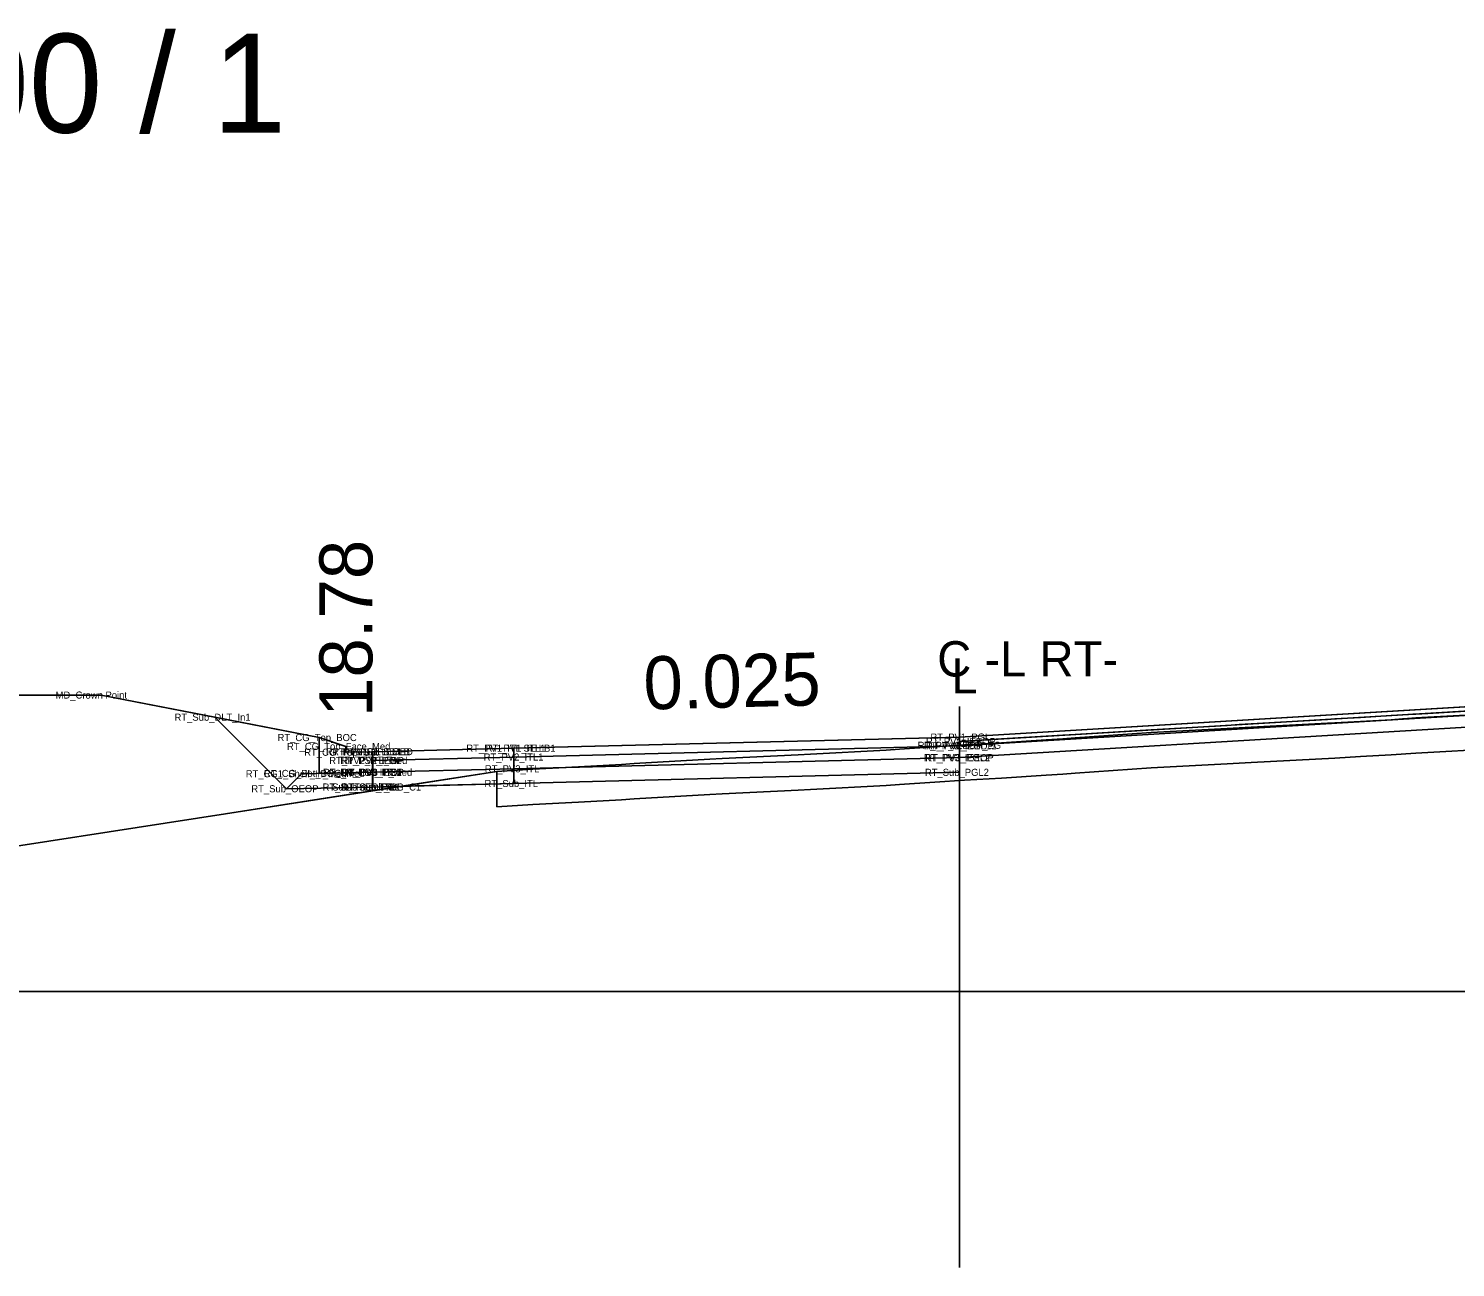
# Model space of a CAD drawing. Extents: x 2177029 to 2201446, y 59897 to 78390.
# Drawn here: x 2199246.36 to 2199286.78, y 67399.49 to 67434.59 of the extents above; entities that cross this region are included whole.
import ezdxf

# ---------------------------------------------------------------- set-up
doc = ezdxf.new("R2010")
doc.units = 0
for name, color, linetype in [('Exist CMT Pavement', 7, 'Continuous'), ('Exist Cross Section Cell', 7, 'Continuous'), ('Exist PHM Roadway Shape', 7, 'Continuous'), ('Exist XS Ground Line', 7, 'Continuous'), ('Old_Level_11', 7, 'Continuous'), ('Prop CMT Conc Surface', 7, 'Continuous'), ('Prop CMT Concrete Structures', 7, 'Continuous'), ('Prop CMT Guardrail Graphics', 7, 'Continuous'), ('Prop CMT Pvmt Course 1 CG', 7, 'Continuous'), ('Prop CMT Pvmt Course 2', 7, 'Continuous'), ('Prop CMT Pvmt Course 2 CG', 7, 'Continuous'), ('Prop CMT Pvmt Course 3', 7, 'Continuous'), ('Prop CMT Pvmt Course 4', 7, 'Continuous'), ('Prop CMT Pvmt Surface', 7, 'Continuous'), ('Prop CMT Pvmt Wedge Surface 1', 7, 'Continuous'), ('Prop CMT Slope Grass', 7, 'Continuous'), ('Prop CMT Subgrade Earthwork', 7, 'Continuous'), ('Prop CMT Top Wall Envelope', 7, 'Continuous'), ('Prop Hatching', 7, 'Continuous'), ('Prop Horizontal Alignment', 7, 'Continuous'), ('Prop Retaining Wall', 7, 'Continuous'), ('Prop Terminator CELL', 7, 'Continuous'), ('Prop XS Side Slope Text', 7, 'Continuous'), ('Scratch_Level_0', 7, 'Continuous'), ('Scratch_Level_9', 7, 'Continuous')]:
    doc.layers.add(name, color=color, linetype=linetype)

msp = doc.modelspace()

# ---------------------------------------------------------------- linework, layer by layer
at = {"layer": 'Exist CMT Pavement'}
msp.add_line((2199272.732, 67399.492), (2199272.732, 67415.386), dxfattribs=at)
at = {"layer": 'Exist Cross Section Cell'}
msp.add_line((2199242.732, 67407.31), (2199442.732, 67407.31), dxfattribs=at)
at = {"layer": 'Exist XS Ground Line'}
msp.add_lwpolyline([(2199243.632, 67411.059), (2199251.936, 67412.347), (2199259.623, 67413.544), (2199260.641, 67413.608), (2199261.941, 67413.677), (2199263.157, 67413.744), (2199263.515, 67413.765), (2199265.656, 67413.889), (2199266.012, 67413.909), (2199268.156, 67414.018), (2199268.509, 67414.036), (2199270.656, 67414.15), (2199271.035, 67414.175), (2199272.036, 67414.242), (2199272.872, 67414.294), (2199273.919, 67414.357), (2199275.187, 67414.441), (2199275.657, 67414.47), (2199276.002, 67414.495), (2199278.157, 67414.645), (2199280.316, 67414.758), (2199280.656, 67414.775), (2199280.996, 67414.794), (2199283.364, 67414.923), (2199284.092, 67414.963), (2199284.953, 67415.01), (2199285.656, 67415.059), (2199285.992, 67415.078), (2199288.156, 67415.199)], dxfattribs=at)
at = {"layer": 'Prop CMT Conc Surface'}
for points in [[(2199272.732, 67414.394), (2199305.082, 67416.335)], [(2199272.732, 67414.519), (2199272.732, 67414.269), (2199272.732, 67414.269), (2199272.732, 67414.394)]]:
    msp.add_lwpolyline(points, dxfattribs=at)
at = {"layer": 'Prop CMT Concrete Structures'}
for p, q in [((2199272.732, 67414.519), (2199308.732, 67416.679)), ((2199272.732, 67414.519), (2199260.112, 67414.203)), ((2199256.102, 67414.103), (2199256.101, 67414.103)), ((2199256.111, 67414.103), (2199256.102, 67414.103)), ((2199260.112, 67414.203), (2199260.11, 67414.203))]:
    msp.add_line(p, q, dxfattribs=at)
at = {"layer": 'Prop CMT Guardrail Graphics'}
for points in [[(2199272.732, 67413.935), (2199308.732, 67416.095)], [(2199272.732, 67414.519), (2199272.732, 67413.935)]]:
    msp.add_lwpolyline(points, dxfattribs=at)
at = {"layer": 'Prop CMT Pvmt Course 1 CG'}
for points in [[(2199256.111, 67413.52), (2199260.11, 67413.62)], [(2199256.111, 67413.103), (2199256.111, 67413.52)], [(2199260.11, 67413.62), (2199260.11, 67413.203)], [(2199260.11, 67413.203), (2199256.111, 67413.103)]]:
    msp.add_lwpolyline(points, dxfattribs=at)
at = {"layer": 'Prop CMT Pvmt Course 2'}
for points in [[(2199272.732, 67413.935), (2199260.11, 67413.62)], [(2199272.732, 67413.519), (2199272.732, 67413.935)], [(2199256.111, 67413.52), (2199256.101, 67413.519)], [(2199256.101, 67413.519), (2199256.101, 67413.103)], [(2199256.111, 67413.103), (2199256.111, 67413.52)], [(2199260.11, 67413.62), (2199260.11, 67413.203)], [(2199260.11, 67413.203), (2199272.732, 67413.519)], [(2199256.101, 67413.103), (2199256.111, 67413.103)]]:
    msp.add_lwpolyline(points, dxfattribs=at)
at = {"layer": 'Prop CMT Pvmt Course 2 CG'}
for points in [[(2199272.732, 67414.519), (2199308.732, 67416.679)], [(2199305.082, 67416.335), (2199272.732, 67414.394)], [(2199272.732, 67414.519), (2199260.11, 67414.203)], [(2199272.732, 67414.269), (2199272.732, 67414.519)], [(2199272.732, 67414.269), (2199272.732, 67414.519)], [(2199256.111, 67414.103), (2199256.101, 67414.103)], [(2199256.101, 67414.103), (2199256.101, 67413.853)], [(2199256.111, 67413.853), (2199256.111, 67414.103)], [(2199260.11, 67413.953), (2199272.732, 67414.269)], [(2199260.11, 67414.203), (2199260.11, 67413.953)], [(2199272.732, 67414.394), (2199272.732, 67414.269), (2199272.732, 67414.269)], [(2199256.101, 67413.853), (2199256.111, 67413.853)]]:
    msp.add_lwpolyline(points, dxfattribs=at)
at = {"layer": 'Prop CMT Pvmt Course 3'}
msp.add_line((2199272.732, 67414.285), (2199272.732, 67413.519), dxfattribs=at)
for points in [[(2199251.64, 67415.08), (2199253.665, 67413.054)], [(2199260.11, 67413.203), (2199272.732, 67413.519)], [(2199256.101, 67413.103), (2199253.665, 67413.054)], [(2199256.111, 67413.103), (2199256.101, 67413.103)], [(2199256.101, 67413.103), (2199256.101, 67413.103)], [(2199260.11, 67413.203), (2199256.111, 67413.103)]]:
    msp.add_lwpolyline(points, dxfattribs=at)
at = {"layer": 'Prop CMT Pvmt Course 4'}
msp.add_lwpolyline([(2199260.11, 67414.203), (2199256.111, 67414.103)], dxfattribs=at)
at = {"layer": 'Prop CMT Pvmt Surface'}
for points in [[(2199272.732, 67414.394), (2199272.872, 67414.403), (2199273.919, 67414.466), (2199275.187, 67414.542), (2199275.657, 67414.57), (2199276.002, 67414.591), (2199278.157, 67414.72), (2199280.316, 67414.849), (2199280.656, 67414.87), (2199280.996, 67414.89), (2199283.156, 67415.02), (2199283.364, 67415.032), (2199284.092, 67415.076), (2199284.953, 67415.128), (2199285.28, 67415.147), (2199285.574, 67415.165), (2199285.656, 67415.17), (2199285.992, 67415.19), (2199288.156, 67415.32)], [(2199288.156, 67415.199), (2199285.992, 67415.078), (2199285.656, 67415.059), (2199285.574, 67415.053), (2199285.28, 67415.032), (2199284.953, 67415.01), (2199284.092, 67414.963), (2199283.364, 67414.923), (2199283.156, 67414.912), (2199280.996, 67414.794), (2199280.656, 67414.775), (2199280.316, 67414.758), (2199278.157, 67414.645), (2199276.002, 67414.495), (2199275.657, 67414.47), (2199275.187, 67414.441), (2199273.919, 67414.357), (2199272.872, 67414.294), (2199272.732, 67414.285)], [(2199272.732, 67414.285), (2199272.732, 67414.394)]]:
    msp.add_lwpolyline(points, dxfattribs=at)
at = {"layer": 'Prop CMT Pvmt Wedge Surface 1'}
for p, q in [((2199285.992, 67414.078), (2199288.156, 67414.199)), ((2199278.157, 67413.645), (2199280.316, 67413.758)), ((2199280.316, 67413.758), (2199280.656, 67413.775)), ((2199280.656, 67413.775), (2199280.996, 67413.794)), ((2199280.996, 67413.794), (2199283.364, 67413.923)), ((2199283.364, 67413.923), (2199284.092, 67413.963)), ((2199284.092, 67413.963), (2199284.953, 67414.01)), ((2199284.953, 67414.01), (2199285.656, 67414.059)), ((2199285.656, 67414.059), (2199285.992, 67414.078)), ((2199259.623, 67412.544), (2199259.623, 67413.544)), ((2199272.036, 67413.242), (2199272.872, 67413.294)), ((2199272.872, 67413.294), (2199273.919, 67413.357)), ((2199273.919, 67413.357), (2199275.187, 67413.441)), ((2199275.187, 67413.441), (2199275.657, 67413.47)), ((2199275.657, 67413.47), (2199276.002, 67413.495)), ((2199276.002, 67413.495), (2199278.157, 67413.645)), ((2199263.515, 67412.765), (2199265.656, 67412.889)), ((2199265.656, 67412.889), (2199266.012, 67412.909)), ((2199266.012, 67412.909), (2199268.156, 67413.018)), ((2199268.156, 67413.018), (2199268.509, 67413.036)), ((2199268.509, 67413.036), (2199270.656, 67413.15)), ((2199270.656, 67413.15), (2199271.035, 67413.175)), ((2199271.035, 67413.175), (2199272.036, 67413.242)), ((2199259.623, 67412.544), (2199260.641, 67412.608)), ((2199260.641, 67412.608), (2199261.941, 67412.677)), ((2199261.941, 67412.677), (2199263.157, 67412.744)), ((2199263.157, 67412.744), (2199263.515, 67412.765))]:
    msp.add_line(p, q, dxfattribs=at)
at = {"layer": 'Prop CMT Slope Grass'}
for points in [[(2199272.732, 67414.269), (2199260.11, 67413.953)], [(2199272.732, 67413.935), (2199272.732, 67414.269)], [(2199256.111, 67413.853), (2199256.101, 67413.853)], [(2199256.101, 67413.853), (2199256.101, 67413.519)], [(2199256.111, 67413.52), (2199256.111, 67413.853)], [(2199260.11, 67413.953), (2199260.11, 67413.62)], [(2199260.11, 67413.62), (2199272.732, 67413.935)], [(2199256.101, 67413.519), (2199256.111, 67413.52)]]:
    msp.add_lwpolyline(points, dxfattribs=at)
at = {"layer": 'Prop CMT Subgrade Earthwork'}
for points in [[(2199272.732, 67414.269), (2199308.732, 67416.429)], [(2199272.732, 67414.519), (2199272.732, 67414.269)]]:
    msp.add_lwpolyline(points, dxfattribs=at)
at = {"layer": 'Prop Hatching'}
for points in [[(2199242.252, 67415.698), (2199248.421, 67415.708)], [(2199254.591, 67414.504), (2199248.421, 67415.708)]]:
    msp.add_lwpolyline(points, dxfattribs=at)
at = {"layer": 'Prop Horizontal Alignment'}
for points in [[(2199256.101, 67413.52), (2199254.091, 67413.479), (2199253.665, 67413.054)], [(2199256.101, 67413.103), (2199256.101, 67413.52)], [(2199253.665, 67413.054), (2199256.101, 67413.103)]]:
    msp.add_lwpolyline(points, dxfattribs=at)
at = {"layer": 'Prop Retaining Wall'}
msp.add_lwpolyline([(2199256.101, 67414.103), (2199255.35, 67414.088), (2199255.35, 67414.254), (2199254.591, 67414.504)], dxfattribs=at)
at = {"layer": 'Prop Terminator CELL'}
for points in [[(2199256.101, 67414.103), (2199255.35, 67414.088), (2199255.35, 67414.254), (2199254.591, 67414.504)], [(2199254.591, 67414.504), (2199254.591, 67413.489)], [(2199256.101, 67413.52), (2199256.101, 67414.103)], [(2199254.591, 67413.489), (2199256.101, 67413.52)]]:
    msp.add_lwpolyline(points, dxfattribs=at)
at = {"layer": 'Prop XS Side Slope Text'}
msp.add_lwpolyline([(2199308.742, 67416.679), (2199272.732, 67414.519), (2199260.11, 67414.203), (2199256.111, 67414.103), (2199255.35, 67414.088), (2199255.35, 67414.254), (2199254.591, 67414.504), (2199251.64, 67415.08), (2199253.665, 67413.054), (2199256.111, 67413.103), (2199256.924, 67413.124), (2199259.623, 67413.544), (2199260.641, 67413.608), (2199261.941, 67413.677), (2199263.157, 67413.744), (2199263.515, 67413.765), (2199265.656, 67413.889), (2199266.012, 67413.909), (2199268.156, 67414.018), (2199268.509, 67414.036), (2199270.656, 67414.15), (2199271.035, 67414.175), (2199272.036, 67414.242), (2199272.732, 67414.285), (2199272.872, 67414.294), (2199273.919, 67414.357), (2199275.187, 67414.441), (2199275.657, 67414.47), (2199276.002, 67414.495), (2199278.157, 67414.645), (2199280.316, 67414.758), (2199280.656, 67414.775), (2199280.996, 67414.794), (2199283.364, 67414.923), (2199284.092, 67414.963), (2199284.953, 67415.01), (2199285.656, 67415.059), (2199285.992, 67415.078), (2199288.156, 67415.199)], dxfattribs=at)
for points in [[(2199256.924, 67413.124), (2199256.111, 67413.103), (2199253.665, 67413.054), (2199251.64, 67415.08), (2199248.421, 67415.708), (2199244.536, 67415.702), (2199243.159, 67414.323), (2199242.732, 67414.313), (2199242.732, 67411.221), (2199243.632, 67411.059), (2199251.936, 67412.347)], [(2199272.732, 67414.285), (2199272.732, 67413.519), (2199260.11, 67413.203), (2199256.924, 67413.124), (2199259.623, 67413.544), (2199260.641, 67413.608), (2199261.941, 67413.677), (2199263.157, 67413.744), (2199263.515, 67413.765), (2199265.656, 67413.889), (2199266.012, 67413.909), (2199268.156, 67414.018), (2199268.509, 67414.036), (2199270.656, 67414.15), (2199271.035, 67414.175), (2199272.036, 67414.242)]]:
    msp.add_lwpolyline(points, close=True, dxfattribs=at)
at = {"layer": 'Scratch_Level_0'}
for points in [[(2199260.11, 67413.953), (2199256.111, 67413.853)], [(2199256.111, 67413.853), (2199256.111, 67413.52)], [(2199260.11, 67413.62), (2199260.11, 67413.953)], [(2199256.111, 67413.52), (2199260.11, 67413.62)]]:
    msp.add_lwpolyline(points, dxfattribs=at)
at = {"layer": 'Scratch_Level_9'}
for points in [[(2199260.11, 67414.203), (2199256.111, 67414.103)], [(2199256.111, 67414.103), (2199256.111, 67413.853)], [(2199260.11, 67413.953), (2199260.11, 67414.203)], [(2199256.111, 67413.853), (2199260.11, 67413.953)]]:
    msp.add_lwpolyline(points, dxfattribs=at)

# ---------------------------------------------------------------- texts
at = {"layer": 'Exist CMT Pavement'}
for s, p in [('C -L RT-', (2199272.099, 67416.234)), ('L', (2199272.502, 67415.753))]:
    msp.add_text(s, height=1, dxfattribs=at).set_placement(p)
at = {"layer": 'Exist Cross Section Cell'}
msp.add_text('36+50.00 / 1', height=2.8, dxfattribs=at).set_placement((2199232.732, 67431.641))
at = {"layer": 'Exist PHM Roadway Shape'}
for s, p in [('MD_Crown Point', (2199247.128, 67415.608)), ('RT_Sub_DLT_In1', (2199250.496, 67414.98)), ('RT_CG_Top_BOC', (2199253.414, 67414.404)), ('RT_PV1_IEEOP', (2199271.78, 67414.294)), ('RT_PV1_PGL', (2199271.906, 67414.419)), ('RT_CG_Top_Face_Med', (2199253.682, 67414.154)), ('RT_CG_Top_Gut', (2199254.169, 67413.988)), ('RT_PV1_ITL SE LB', (2199254.785, 67414.003)), ('RT_PV1_ITL_MED', (2199254.959, 67414.003)), ('RT_PS1_IEOP', (2199255.251, 67414.003)), ('RT_PV1_ITL SE LB1', (2199258.762, 67414.103)), ('RT_PV1_ITL1', (2199259.309, 67414.103)), ('RT_PV_IEEOP_EG', (2199271.546, 67414.185)), ('RT_PV2_IEEOP', (2199271.723, 67414.169)), ('RT_PV2_PGL11', (2199271.783, 67414.169)), ('RT_PV2_ITL_med', (2199254.878, 67413.753)), ('RT_PS2_IEOP', (2199255.194, 67413.753)), ('RT_PV2_PGL', (2199255.227, 67413.753)), ('RT_PV2_ITL1', (2199259.252, 67413.853)), ('RT_PV3_ITL', (2199259.285, 67413.52)), ('RT_PV3_IEEOP', (2199271.723, 67413.835)), ('RT_PV3_PGL2', (2199271.759, 67413.835)), ('RT_CG1_Shelf_In_Med', (2199252.514, 67413.379)), ('RT_CG_Bot_BOC_Med', (2199253.028, 67413.389)), ('RT_CG_Bot_IE_Med', (2199254.702, 67413.42)), ('RT_PS3_IEOP', (2199255.194, 67413.42)), ('RT_PV3_PGL', (2199255.227, 67413.42)), ('RT_PV3_ITL1', (2199255.242, 67413.419)), ('RT_Sub_ITL', (2199259.276, 67413.103)), ('RT_Sub_PGL2', (2199271.75, 67413.419)), ('RT_Sub_OEOP', (2199252.671, 67412.954)), ('RT_Sub_IEOT_CG_C1', (2199254.688, 67413.003)), ('Sub_Trench_In', (2199254.963, 67413.003)), ('RT_Sub_PGL', (2199255.218, 67413.003)), ('RT_Sub_ITL1', (2199255.233, 67413.003))]:
    msp.add_text(s, height=0.2, dxfattribs=at).set_placement(p)
at = {"layer": 'Old_Level_11'}
msp.add_text('0.025', height=1.5, rotation=1.4342, dxfattribs=at).set_placement((2199263.796, 67415.296))
at = {"layer": 'Prop CMT Top Wall Envelope'}
msp.add_text('18.78', height=1.5, rotation=90, dxfattribs=at).set_placement((2199256.1, 67415.088))

doc.saveas('drawing.dxf')
